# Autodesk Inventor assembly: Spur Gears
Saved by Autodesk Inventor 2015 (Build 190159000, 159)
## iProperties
Created: 2014-08
Part Number: Spur Gears
Document SubType Name: Assembly
Designer: User
Categories: <?xml version="1.0" encoding="UTF-16"?> <MemberInstance><Categories><FamilyTemplate/><ParamToTemplateMap><ParamToTemplate><ParamToTemplate CategoryParameter="//
ClientObjectVersion: 1
Author: User
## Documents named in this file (3)
- Z:\CAD Files\Gears\Helical_Gear_Assembly\Design Accelerator\Spur Gears1.iam
- Z:\CAD Files\Gears\Helical_Gear_Assembly\Design Accelerator\Spur Gear11.ipt
- Z:\CAD Files\Gears\Helical_Gear_Assembly\Design Accelerator\Spur Gear21.ipt
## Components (2 placed, 2 different names)
1. Spur Gear1:1 — Rotation:1
2. Spur Gear2:1 — Rotation:1
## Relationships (1: RelateRotation 1)
- Rotation:1 [RelateRotation]: Spur Gear1:1 ↔ Spur Gear2:1
